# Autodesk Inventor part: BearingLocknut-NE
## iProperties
Author: Gerald L. Pierce
Shininess: 86.0
PropertySet Name: _Private Model Information
Created: 2001-01
Part Number: BearingLocknut-NE
Material: Steel, Mild
Document SubType Name: Modeling
Designer: Gerald L. Pierce
Control State: 0
Master: False
Checked Out: False
PropertySet Name: Design Tracking Control
Density: 7.859999999999999
Volumn: 32.75577793121353
Area: 116.51683115369147
PropertySet Name: Model Information
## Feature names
1. Body [Extrusion]
2. Chamfer1
3. SpannerSlot [Extrusion]
4. Circular Pattern1
5. Chamfer2
